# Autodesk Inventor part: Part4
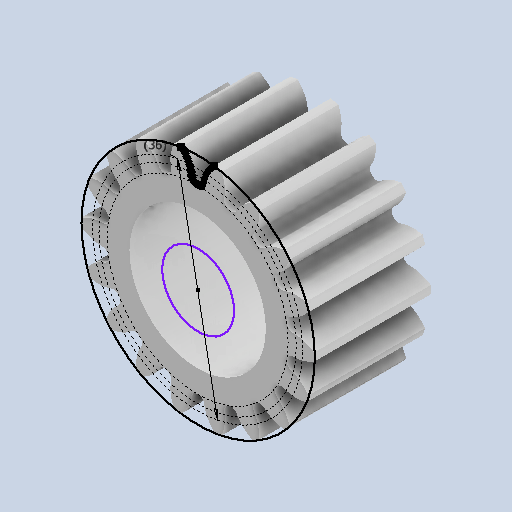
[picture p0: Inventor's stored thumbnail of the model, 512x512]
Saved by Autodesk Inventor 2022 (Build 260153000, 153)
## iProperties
Created: 2021-07
Part Number: Part4
Material: Generic
Document SubType Name: Modeling
Designer: adams
Density: 1 g/cm^3
Appearance: Default
Author: adams
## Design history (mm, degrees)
sketch "Sketch1"
  geometry: C1 r 15.5 at (0, 0) reference; C2 r 16.914 at (0, 0) reference; C3 r 18 at (0, 0) reference; C4 r 6.168 at (0, 0); A1 r 20 centre (0, 0) between (-2.8, 19.803) and (2.8, 19.803) reference; 52 further points
  constraints: 5 centre point, 2 point on circle, 1 coincident, 111 other
  dimensions: "d7" = 36 diameter of C3 (derived)
extrude "Extrusion1" join sketch "Sketch1" distance "d0" = 20 (= FaceWidth); taper "d1" = 0 deg
extrude "Extrusion2" cut sketch "Sketch1" extent not by distance; stored distance "d2" = 0; taper "d3" = 0 deg
extrude "Extrusion3" cut sketch "Sketch1" extent not by distance; stored distance "d8" = 0; taper "d9" = 0 deg
sketch "Sketch2"
  geometry: C1 r 11.691 at (0, 0); 1 further point
  constraints: 1 centre point, 1 coincident
extrude "Extrusion4" cut sketch "Sketch2" extent not by distance; stored distance "d10" = 0; taper "d11" = 0 deg
body "Solid1"
pattern_circular "Circular Pattern1" dims angle "d5" = 360 deg
other parameters: "Module" = 2 [user parameter], "PressureAngle" = 20 deg [user parameter], "UnitProfileClearance" = 2.5 [user parameter], "UnitRoundRadius" = 3.5 [user parameter], "RootDiameter" = 31 [user parameter], "BaseDiameter" = 33.82893 [user parameter], "PitchDiameter" = 36 [user parameter], "FaceWidth" = 20 [user parameter; used in 1 equation term], "HelixAngle" = 0 [user parameter], "UnitCorrection" = 0 [user parameter], "UnitAddendumModification" = 0 [user parameter], "CircularPitch" = 36 deg [user parameter], "UnitBacklashShift" = 0 [user parameter], "TotalToolShift" = 0 [user parameter], "IsInternal" = 0 [user parameter]
